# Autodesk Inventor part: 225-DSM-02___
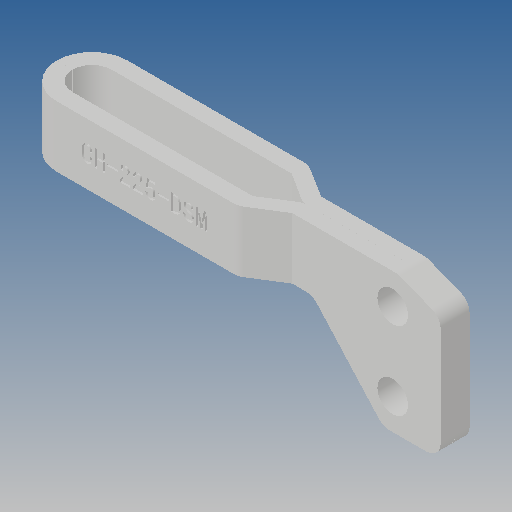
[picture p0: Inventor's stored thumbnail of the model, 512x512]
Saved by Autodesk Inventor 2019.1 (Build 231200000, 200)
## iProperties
Created: 2010-06
Part Number: 225-DSM-02___
Material: Ogólny
Document SubType Name: Modeling
Designer: CADENGINEERING4
Density: 1 g/cm^3
Appearance: Domyślna
Author: CADENGINEERING4
Revision Number: ANY
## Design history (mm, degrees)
feature "NONE"
feature "NONE:1"
node "Bryła1"
node "Bryła2"
